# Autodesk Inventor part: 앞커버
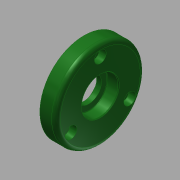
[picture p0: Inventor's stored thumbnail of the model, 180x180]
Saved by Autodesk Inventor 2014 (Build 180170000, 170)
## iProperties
Created: 2015-11
Part Number: 앞커버
Material: 알루미늄 6061
Document SubType Name: Modeling
Designer: mduedu
Density: 1 g/cm^3
Appearance: 매끄러움 - 짙은 산림 녹색
Author: mduedu
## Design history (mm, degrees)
sketch "스케치5"
  geometry: C1 r 30 at (0, 0); 2 further points
  constraints: 2 coincident, 1 centre point
  dimensions: "d66" = 60 diameter of C1
extrude "돌출2" new body sketch "스케치5" distance "d67" = 11; taper "d68" = 0 deg
sketch "스케치6"
  geometry: C1 r 16 at (0, 0); 1 further point
  constraints: 1 centre point, 1 coincident
  dimensions: "d69" = 32 diameter of C1
extrude "돌출3" join sketch "스케치6" distance "d70" = 3; taper "d71" = 0 deg
hole "구멍7" diameter "d98" = 25; stored, may be unused: countersink angle "d102" = 90 deg, drill point angle "d104" = 0 deg; dims "d96" = 10, "d97" = 10, "d99" = 6, "d100" = 4, "d101" = 2, "d103" = 3
hole "구멍8" diameter "d107" = 25; stored, may be unused: countersink angle "d111" = 90 deg, drill point angle "d113" = 0 deg; dims "d105" = 10, "d106" = 10, "d108" = 6, "d109" = 4, "d110" = 2, "d112" = 7.7
hole "구멍9" diameter "d116" = 17; stored, may be unused: countersink angle "d120" = 90 deg, drill point angle "d122" = 0 deg; dims "d114" = 10, "d115" = 10, "d117" = 6, "d118" = 4, "d119" = 2, "d121" = 7.7
chamfer "모따기2" distance "d123" = 0.6; stored, may be unused: second distance "d124" = 2, angle "d125" = 30 deg
fillet "모깎기11" dims "d126" = 0.3
fillet "모깎기13" dims "d128" = 3
fillet "모깎기14" dims "d129" = 3
fillet "모깎기15" dims "d130" = 0.3
sketch "스케치8" dims "d131" = 46
  geometry: 3 further points
  constraints: 2 vertical alignment, 1 coincident, 2 other
hole "구멍10" sketch "스케치8" at (0, 23) diameter "d132" = 4.5; stored, may be unused: countersink angle "d136" = 90 deg, drill point angle "d138" = 0 deg; dims "d133" = 6, "d134" = 8, "d135" = 4.6, "d137" = 7.7
node "솔리드2"
pattern_circular "원형 패턴4" dims angle "d140" = 360 deg
